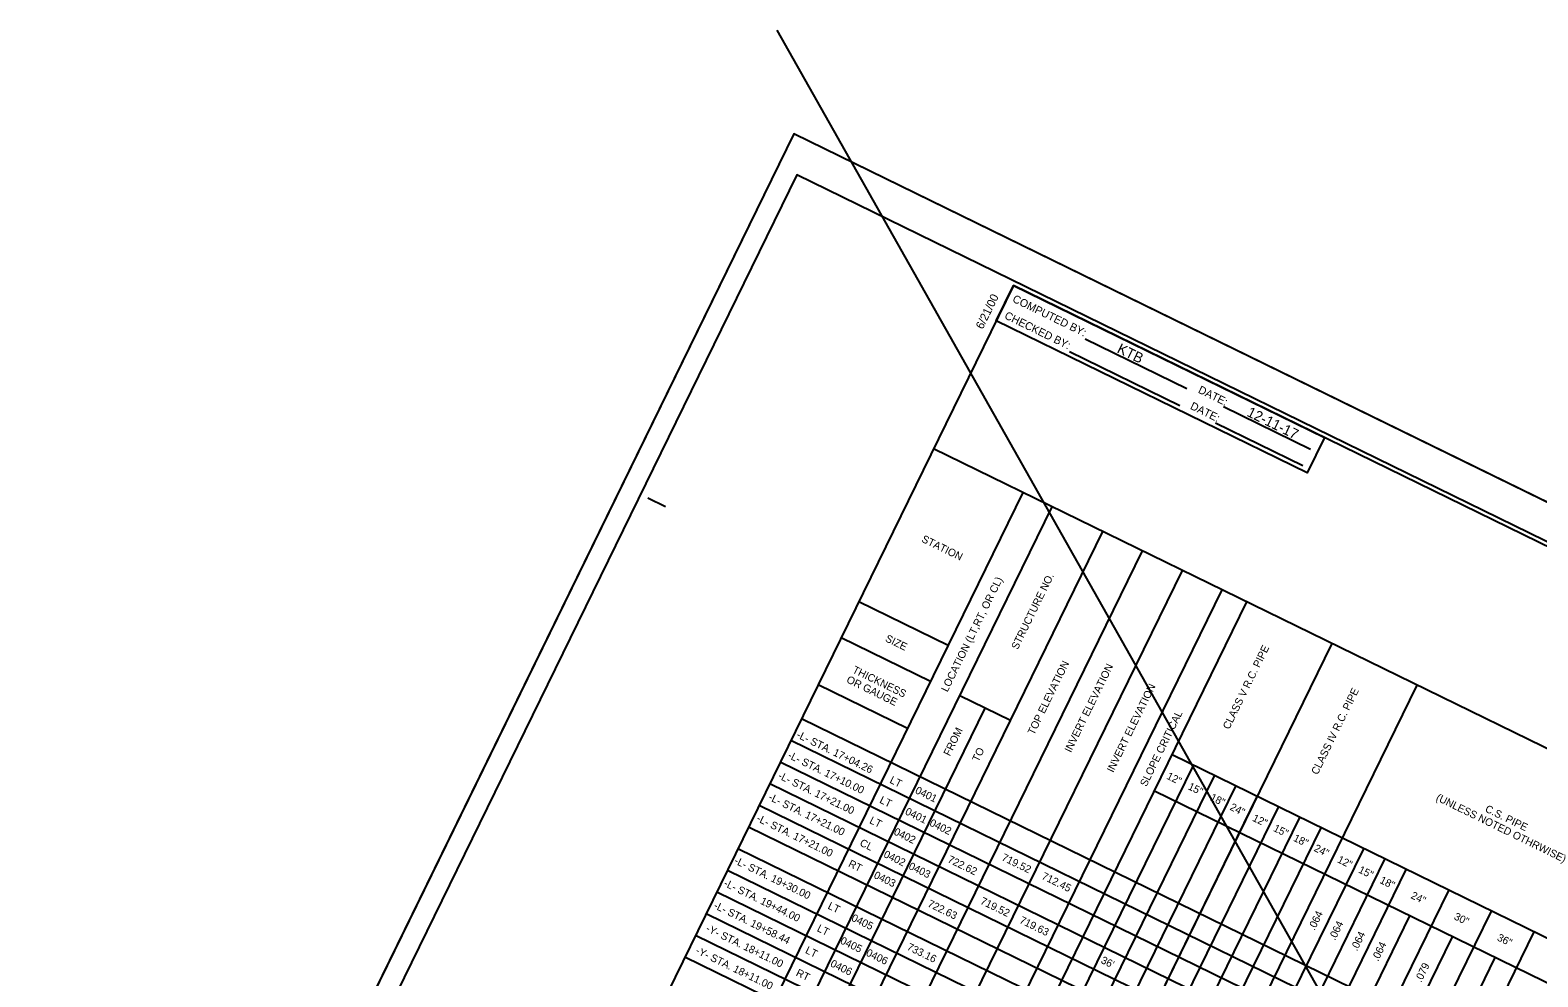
# Model space of a CAD drawing. Extents: x 1523741 to 1527628, y 632733 to 635404.
# Drawn here: x 1523818 to 1524772, y 634805 to 635404 of the extents above; entities that cross this region are included whole.
import ezdxf

# ---------------------------------------------------------------- set-up
doc = ezdxf.new("R2010")
doc.units = 0
for name, color, linetype in [('Scratch_Level_0', 7, 'Continuous'), ('Sheet Cutting Line CELL', 7, 'Continuous'), ('Sheet Pipe Summary CELL', 7, 'Continuous'), ('Sheet Pipe Summary Grid CELL', 7, 'Continuous'), ('Sheet Plot Border Inside CELL', 7, 'Continuous'), ('Sheet Plot Border Outside CELL', 7, 'Continuous'), ('Sheet Summary Combination CELL', 7, 'Continuous')]:
    doc.layers.add(name, color=color, linetype=linetype)

msp = doc.modelspace()

# ---------------------------------------------------------------- linework, layer by layer
at = {"layer": 'Scratch_Level_0'}
msp.add_line((1525401.79, 633436.57), (1524290.22, 635404.2), dxfattribs=at)
at = {"layer": 'Sheet Cutting Line CELL'}
for p, q in [((1524300.78, 635338.51), (1523817.5, 634350.36)), ((1525813.55, 634598.64), (1524300.78, 635338.51))]:
    msp.add_line(p, q, dxfattribs=at)
at = {"layer": 'Sheet Pipe Summary Grid CELL'}
for p, q in [((1525736.78, 634480.36), (1524389.26, 635139.29)), ((1524181.28, 634570.7), (1524445.8, 635111.64)), ((1524199.74, 634561.67), (1524464.27, 635102.61)), ((1524231.86, 634545.97), (1524496.38, 635086.9)), ((1524256.99, 634533.68), (1524521.51, 635074.61)), ((1524282.12, 634521.39), (1524546.64, 635062.32)), ((1524307.25, 634509.09), (1524571.77, 635050.03)), ((1524322.97, 634501.41), (1524587.49, 635042.35)), ((1524398.42, 635014.75), (1524341.87, 635042.41)), ((1524387.26, 634991.94), (1524330.71, 635019.59)), ((1524376.87, 634475.04), (1524641.4, 635016)), ((1524372.7, 634962.16), (1524316.15, 634989.81)), ((1524430.76, 634448.68), (1524695.3, 634989.64)), ((1524437.85, 634967.2), (1524405.73, 634982.9)), ((1524215.82, 634553.81), (1524421.8, 634975.04)), ((1525653.12, 634309.32), (1524305.65, 634968.34)), ((1525646.4, 634295.58), (1524298.93, 634954.6)), ((1525639.7, 634281.88), (1524292.23, 634940.9)), ((1524336.44, 634494.82), (1524553.59, 634938.87)), ((1524941.69, 634749.13), (1524540.12, 634945.46)), ((1524349.92, 634488.23), (1524567.07, 634932.28)), ((1525633, 634268.18), (1524285.53, 634927.2)), ((1524363.39, 634481.64), (1524580.54, 634925.69)), ((1524376.87, 634475.05), (1524594.02, 634919.1)), ((1524930.53, 634726.31), (1524528.96, 634922.66)), ((1525626.28, 634254.44), (1524278.8, 634913.46)), ((1524390.34, 634468.45), (1524607.49, 634912.52)), ((1525619.58, 634240.74), (1524272.1, 634899.76)), ((1524403.82, 634461.86), (1524620.97, 634905.93)), ((1524417.29, 634455.27), (1524634.44, 634899.34)), ((1525612.88, 634227.04), (1524265.4, 634886.06)), ((1524444.24, 634442.09), (1524661.39, 634886.16)), ((1525606.18, 634213.34), (1524258.7, 634872.36)), ((1524457.71, 634435.5), (1524674.87, 634879.57)), ((1524471.19, 634428.91), (1524688.34, 634872.98)), ((1525599.48, 634199.64), (1524252, 634858.66)), ((1524498.14, 634415.73), (1524715.29, 634859.8)), ((1525592.78, 634185.94), (1524245.3, 634844.96)), ((1524484.66, 634422.32), (1524690.67, 634843.59)), ((1524525.09, 634402.55), (1524742.24, 634846.62)), ((1524552.04, 634389.37), (1524769.19, 634833.44)), ((1525586.08, 634172.24), (1524238.6, 634831.26)), ((1524511.61, 634409.14), (1524717.62, 634830.41)), ((1525579.38, 634158.54), (1524231.9, 634817.56)), ((1524538.56, 634395.96), (1524744.57, 634817.24))]:
    msp.add_line(p, q, dxfattribs=at)
at = {"layer": 'Sheet Plot Border Inside CELL'}
msp.add_lwpolyline([(1525799.64, 634580.45), (1524302.6, 635312.63), (1523839.04, 634364.81), (1525336.09, 633632.64)], close=True, dxfattribs=at)
at = {"layer": 'Sheet Plot Border Outside CELL'}
msp.add_lwpolyline([(1525813.55, 634598.64), (1524300.78, 635338.51), (1523817.5, 634350.36), (1525330.27, 633610.5)], close=True, dxfattribs=at)
at = {"layer": 'Sheet Summary Combination CELL'}
for p, q in [((1524485.24, 635208.89), (1524549.51, 635177.45)), ((1524475.2, 635200.77), (1524545, 635166.63)), ((1524572.63, 635165.98), (1524627.78, 635139)), ((1524567.71, 635155.58), (1524622.86, 635128.61)), ((1524208.3, 635108.22), (1524219.53, 635102.73))]:
    msp.add_line(p, q, dxfattribs=at)
for points in [[(1525787.29, 634583.66), (1524439.82, 635242.68), (1523978.5, 634299.44), (1525325.98, 633640.42)], [(1524439.82, 635242.68), (1524636.55, 635146.46), (1524625.57, 635124), (1524428.83, 635220.22)]]:
    msp.add_lwpolyline(points, close=True, dxfattribs=at)

# ---------------------------------------------------------------- texts
at = {"layer": 'Sheet Pipe Summary CELL'}
for s, rotation, p in [('STATION', 333.93772, (1524381.18, 635080.57)), ('LOCATION (LT,RT, OR CL)', 63.93772, (1524397.99, 634984.96)), ('STRUCTURE NO.', 63.93772, (1524442.41, 635011.72)), ('SIZE', 333.93772, (1524358.19, 635017.62)), ('CLASS V R.C. PIPE', 63.93772, (1524576.26, 634961.22)), ('TOP ELEVATION', 63.93772, (1524452.76, 634957.76)), ('OR GAUGE', 333.93772, (1524333.66, 634991.6)), ('THICKNESS', 333.93772, (1524337.41, 634997.78)), ('INVERT ELEVATION', 63.93772, (1524476.11, 634946.65)), ('INVERT ELEVATION', 63.93772, (1524502.93, 634933.98)), ('CLASS IV R.C. PIPE', 63.93772, (1524632.21, 634932.53)), ('SLOPE CRITICAL', 63.93772, (1524523.9, 634925.06)), ('FROM', 63.93772, (1524399.51, 634944.37)), ('TO', 63.93772, (1524417.63, 634940.68)), ('12"', 333.93772, (1524536.22, 634930.56)), ('15"', 333.93772, (1524549.75, 634923.94)), ('18"', 333.93772, (1524563.75, 634917.1)), ('(UNLESS NOTED OTHRWISE)', 333.93772, (1524706.72, 634916.97)), ('24"', 333.93772, (1524576.3, 634910.96)), ('C.S. PIPE', 333.93772, (1524737.79, 634909.79)), ('12"', 333.93772, (1524590.53, 634904)), ('15"', 333.93772, (1524603.8, 634897.51)), ('18"', 333.93772, (1524616.44, 634891.33)), ('24"', 333.93772, (1524629.54, 634884.92)), ('12"', 333.93772, (1524644.26, 634877.72)), ('15"', 333.93772, (1524657.59, 634871.26)), ('18"', 333.93772, (1524671.12, 634864.64)), ('24"', 333.93772, (1524690.79, 634855.02)), ('.064', 63.93772, (1524630.29, 634834.07)), ('30"', 333.93772, (1524718.09, 634841.67)), ('.064', 63.93772, (1524643.28, 634827.72)), ('.064', 63.93772, (1524657.17, 634821.03)), ('36"', 333.93772, (1524745.39, 634828.32)), ('.064', 63.93772, (1524670.48, 634814.53)), ('.079', 63.93772, (1524697.78, 634801.18))]:
    msp.add_text(s, height=4.8, rotation=rotation, dxfattribs=at).set_placement(p)
at = {"layer": 'Sheet Summary Combination CELL'}
for s, height, rotation, p in [('6/21/00', 5.25, 63.93772, (1524420.31, 635214.51)), ('COMPUTED BY:', 4.9998, 333.93772, (1524438.68, 635232.49)), ('CHECKED BY:', 4.9998, 333.93772, (1524433.63, 635221.94)), ('KTB', 6.48, 333.93772, (1524504.83, 635200.45)), ('DATE:', 5, 333.93772, (1524556.18, 635174.91)), ('DATE:', 5, 333.93772, (1524551.17, 635164.67)), ('12-11-17', 6.48, 333.93772, (1524586.95, 635160.25)), ('-L- STA. 17+04.26', 4.8, 333.93772, (1524302.03, 634956.74)), ('-L- STA. 17+10.00', 4.8, 333.93772, (1524296.54, 634943.77)), ('-L- STA. 17+21.00', 4.8, 333.93772, (1524290.37, 634930.82)), ('LT', 4.8, 333.93772, (1524361.01, 634928.02)), ('-L- STA. 17+21.00', 4.8, 333.93772, (1524284.3, 634917.26)), ('LT', 4.8, 333.93772, (1524354.62, 634915.41)), ('0401', 4.8, 333.93772, (1524377.13, 634921.52)), ('0401', 4.8, 333.93772, (1524370.78, 634908.13)), ('-L- STA. 17+21.00', 4.8, 333.93772, (1524276.74, 634903.83)), ('LT', 4.8, 333.93772, (1524348.24, 634902.5)), ('0402', 4.8, 333.93772, (1524363.58, 634895.35)), ('0402', 4.8, 333.93772, (1524386.22, 634900.96)), ('CL', 4.8, 333.93772, (1524342.06, 634888.29)), ('-L- STA. 19+30.00', 4.8, 333.93772, (1524262.62, 634877.04)), ('0402', 4.8, 333.93772, (1524357.15, 634881.09)), ('722.62', 4.8, 333.93772, (1524397.65, 634877.81)), ('719.52', 4.8, 333.93772, (1524431.83, 634879.04)), ('RT', 4.8, 333.93772, (1524334.82, 634875.07)), ('0403', 4.8, 333.93772, (1524350.95, 634867.87)), ('0403', 4.8, 333.93772, (1524372.96, 634873.55)), ('712.45', 4.8, 333.93772, (1524457.17, 634867.21)), ('-L- STA. 19+44.00', 4.8, 333.93772, (1524256.02, 634862.76)), ('-L- STA. 19+58.44', 4.8, 333.93772, (1524249.69, 634848.64)), ('LT', 4.8, 333.93772, (1524321.85, 634848.4)), ('722.63', 4.8, 333.93772, (1524385.02, 634849.8)), ('719.52', 4.8, 333.93772, (1524418.34, 634851.46)), ('0405', 4.8, 333.93772, (1524336.74, 634840.79)), ('719.63', 4.8, 333.93772, (1524443.11, 634839.35)), ('-Y- STA. 18+11.00', 4.8, 333.93772, (1524244.71, 634834.16)), ('LT', 4.8, 333.93772, (1524315.02, 634834.15)), ('-Y- STA. 18+11.00', 4.8, 333.93772, (1524238.19, 634820.14)), ('LT', 4.8, 333.93772, (1524307.6, 634820.32)), ('0405', 4.8, 333.93772, (1524329.7, 634826.39)), ('0406', 4.8, 333.93772, (1524346.01, 634818.75)), ('733.16', 4.8, 333.93772, (1524371.93, 634822.42)), ('0406', 4.8, 333.93772, (1524323.43, 634811.91)), ("36'", 4.8, 333.93772, (1524494.6, 634814.03)), ('RT', 4.8, 333.93772, (1524301.72, 634806.03))]:
    msp.add_text(s, height=height, rotation=rotation, dxfattribs=at).set_placement(p)

doc.saveas('drawing.dxf')
